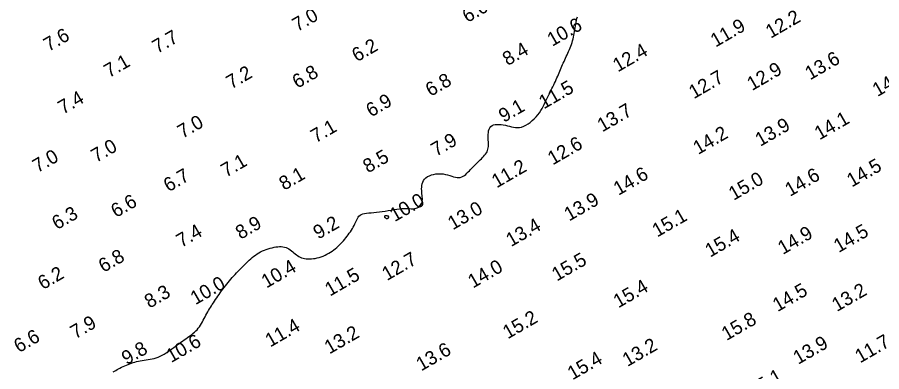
# Model space of a CAD drawing. Extents: x 3024098 to 3056816, y 418252 to 509144.
# Drawn here: x 3034302.4 to 3034614.7, y 418892.7 to 419020.7 of the extents above; entities that cross this region are included whole.
import ezdxf

# ---------------------------------------------------------------- set-up
doc = ezdxf.new("R2010")
doc.units = 0
doc.layers.add('V-CHAN-CONT-EL10', color=7, linetype='Continuous')
doc.layers.add('V-TOPO-SOUN-0911', color=7, linetype='Continuous')

msp = doc.modelspace()

# ---------------------------------------------------------------- linework, layer by layer
at = {"layer": 'V-CHAN-CONT-EL10'}
msp.add_lwpolyline([(3034337.08, 418892.58), (3034337.52, 418892.88), (3034337.98, 418893.16), (3034338.47, 418893.45), (3034338.98, 418893.74), (3034339.52, 418894.02), (3034340.08, 418894.3), (3034340.65, 418894.57), (3034341.24, 418894.83), (3034341.83, 418895.09), (3034342.44, 418895.33), (3034343.04, 418895.56), (3034343.65, 418895.78), (3034344.27, 418895.98), (3034344.9, 418896.17), (3034345.53, 418896.34), (3034346.18, 418896.5), (3034346.85, 418896.64), (3034347.53, 418896.77), (3034348.23, 418896.87), (3034348.94, 418896.97), (3034349.67, 418897.08), (3034350.4, 418897.19), (3034351.14, 418897.33), (3034351.88, 418897.49), (3034352.62, 418897.7), (3034353.36, 418897.96), (3034354.08, 418898.27), (3034354.8, 418898.64), (3034355.51, 418899.05), (3034356.21, 418899.49), (3034356.91, 418899.96), (3034357.59, 418900.44), (3034358.26, 418900.93), (3034358.93, 418901.43), (3034359.59, 418901.91), (3034360.23, 418902.39), (3034360.87, 418902.85), (3034361.5, 418903.31), (3034362.11, 418903.75), (3034362.71, 418904.18), (3034363.3, 418904.6), (3034363.87, 418905.01), (3034364.43, 418905.4), (3034364.97, 418905.78), (3034365.49, 418906.17), (3034366, 418906.56), (3034366.48, 418906.97), (3034366.94, 418907.4), (3034367.39, 418907.86), (3034367.81, 418908.35), (3034368.21, 418908.89), (3034368.59, 418909.45), (3034368.95, 418910.05), (3034369.29, 418910.66), (3034369.62, 418911.29), (3034369.95, 418911.91), (3034370.27, 418912.53), (3034370.58, 418913.13), (3034370.89, 418913.72), (3034371.21, 418914.28), (3034371.52, 418914.83), (3034371.85, 418915.38), (3034372.18, 418915.92), (3034372.52, 418916.46), (3034372.88, 418917.01), (3034373.25, 418917.57), (3034373.63, 418918.15), (3034374.03, 418918.74), (3034374.45, 418919.35), (3034374.88, 418919.96), (3034375.32, 418920.58), (3034375.77, 418921.21), (3034376.23, 418921.84), (3034376.69, 418922.47), (3034377.17, 418923.09), (3034377.65, 418923.72), (3034378.13, 418924.33), (3034378.62, 418924.94), (3034379.11, 418925.54), (3034379.6, 418926.13), (3034380.1, 418926.71), (3034380.6, 418927.27), (3034381.11, 418927.82), (3034381.61, 418928.36), (3034382.12, 418928.88), (3034382.63, 418929.4), (3034383.14, 418929.91), (3034383.65, 418930.42), (3034384.15, 418930.93), (3034384.67, 418931.43), (3034385.18, 418931.94), (3034385.69, 418932.45), (3034386.21, 418932.95), (3034386.74, 418933.44), (3034387.28, 418933.91), (3034387.85, 418934.37), (3034388.43, 418934.81), (3034389.03, 418935.22), (3034389.66, 418935.6), (3034390.31, 418935.95), (3034390.99, 418936.27), (3034391.67, 418936.56), (3034392.37, 418936.82), (3034393.07, 418937.06), (3034393.77, 418937.27), (3034394.47, 418937.45), (3034395.16, 418937.6), (3034395.84, 418937.72), (3034396.5, 418937.81), (3034397.15, 418937.86), (3034397.78, 418937.86), (3034398.39, 418937.81), (3034398.97, 418937.7), (3034399.52, 418937.54), (3034400.05, 418937.31), (3034400.54, 418937.03), (3034401.02, 418936.71), (3034401.48, 418936.36), (3034401.92, 418935.99), (3034402.36, 418935.62), (3034402.8, 418935.26), (3034403.24, 418934.91), (3034403.69, 418934.6), (3034404.15, 418934.32), (3034404.63, 418934.07), (3034405.12, 418933.86), (3034405.64, 418933.69), (3034406.18, 418933.56), (3034406.76, 418933.46), (3034407.36, 418933.41), (3034408, 418933.4), (3034408.68, 418933.43), (3034409.37, 418933.51), (3034410.08, 418933.62), (3034410.8, 418933.77), (3034411.52, 418933.96), (3034412.23, 418934.18), (3034412.94, 418934.45), (3034413.62, 418934.74), (3034414.28, 418935.07), (3034414.93, 418935.43), (3034415.55, 418935.81), (3034416.15, 418936.22), (3034416.73, 418936.64), (3034417.29, 418937.09), (3034417.83, 418937.54), (3034418.35, 418938.01), (3034418.85, 418938.49), (3034419.34, 418938.97), (3034419.81, 418939.47), (3034420.26, 418939.98), (3034420.7, 418940.5), (3034421.13, 418941.03), (3034421.55, 418941.57), (3034421.96, 418942.12), (3034422.36, 418942.67), (3034422.75, 418943.23), (3034423.12, 418943.8), (3034423.46, 418944.36), (3034423.79, 418944.92), (3034424.09, 418945.48), (3034424.36, 418946.03), (3034424.6, 418946.57), (3034424.82, 418947.09), (3034425.04, 418947.58), (3034425.27, 418948.04), (3034425.54, 418948.47), (3034425.86, 418948.85), (3034426.24, 418949.18), (3034426.71, 418949.45), (3034427.26, 418949.66), (3034427.9, 418949.81), (3034428.63, 418949.93), (3034429.43, 418950.01), (3034430.3, 418950.09), (3034431.22, 418950.16), (3034432.2, 418950.25), (3034433.22, 418950.36), (3034434.28, 418950.51), (3034435.36, 418950.68), (3034436.44, 418950.87), (3034437.51, 418951.06), (3034438.56, 418951.24), (3034439.56, 418951.4), (3034440.51, 418951.53), (3034441.39, 418951.62), (3034442.18, 418951.65), (3034442.9, 418951.64), (3034443.54, 418951.61), (3034444.13, 418951.56), (3034444.67, 418951.52), (3034445.16, 418951.5), (3034445.63, 418951.51), (3034446.08, 418951.57), (3034446.51, 418951.69), (3034446.92, 418951.87), (3034447.31, 418952.11), (3034447.67, 418952.39), (3034447.98, 418952.72), (3034448.25, 418953.08), (3034448.47, 418953.48), (3034448.63, 418953.91), (3034448.73, 418954.35), (3034448.77, 418954.83), (3034448.77, 418955.32), (3034448.73, 418955.83), (3034448.68, 418956.36), (3034448.62, 418956.92), (3034448.56, 418957.5), (3034448.52, 418958.09), (3034448.5, 418958.71), (3034448.52, 418959.33), (3034448.59, 418959.95), (3034448.72, 418960.57), (3034448.92, 418961.16), (3034449.19, 418961.72), (3034449.56, 418962.23), (3034450.03, 418962.7), (3034450.61, 418963.11), (3034451.28, 418963.45), (3034452.03, 418963.73), (3034452.83, 418963.94), (3034453.67, 418964.08), (3034454.54, 418964.16), (3034455.41, 418964.16), (3034456.26, 418964.08), (3034457.08, 418963.94), (3034457.87, 418963.74), (3034458.63, 418963.52), (3034459.35, 418963.29), (3034460.04, 418963.07), (3034460.69, 418962.9), (3034461.32, 418962.79), (3034461.9, 418962.76), (3034462.46, 418962.84), (3034462.98, 418963.01), (3034463.48, 418963.26), (3034463.96, 418963.58), (3034464.42, 418963.95), (3034464.87, 418964.36), (3034465.31, 418964.8), (3034465.75, 418965.25), (3034466.18, 418965.7), (3034466.61, 418966.15), (3034467.04, 418966.59), (3034467.48, 418967.03), (3034467.91, 418967.46), (3034468.34, 418967.89), (3034468.77, 418968.32), (3034469.21, 418968.74), (3034469.65, 418969.16), (3034470.08, 418969.57), (3034470.5, 418969.99), (3034470.89, 418970.4), (3034471.26, 418970.82), (3034471.59, 418971.24), (3034471.89, 418971.66), (3034472.13, 418972.1), (3034472.31, 418972.55), (3034472.45, 418973.01), (3034472.54, 418973.48), (3034472.6, 418973.98), (3034472.62, 418974.51), (3034472.62, 418975.06), (3034472.61, 418975.65), (3034472.58, 418976.28), (3034472.56, 418976.94), (3034472.55, 418977.63), (3034472.56, 418978.32), (3034472.61, 418979), (3034472.71, 418979.64), (3034472.88, 418980.23), (3034473.14, 418980.76), (3034473.48, 418981.2), (3034473.93, 418981.53), (3034474.46, 418981.77), (3034475.08, 418981.92), (3034475.76, 418981.99), (3034476.48, 418982), (3034477.23, 418981.94), (3034477.99, 418981.84), (3034478.75, 418981.69), (3034479.5, 418981.52), (3034480.23, 418981.33), (3034480.96, 418981.15), (3034481.68, 418980.99), (3034482.4, 418980.89), (3034483.13, 418980.85), (3034483.87, 418980.89), (3034484.62, 418981.04), (3034485.4, 418981.31), (3034486.18, 418981.69), (3034486.96, 418982.17), (3034487.73, 418982.72), (3034488.48, 418983.35), (3034489.19, 418984.02), (3034489.87, 418984.73), (3034490.48, 418985.47), (3034491.04, 418986.21), (3034491.54, 418986.96), (3034491.99, 418987.71), (3034492.4, 418988.47), (3034492.79, 418989.22), (3034493.15, 418989.96), (3034493.5, 418990.7), (3034493.84, 418991.43), (3034494.19, 418992.15), (3034494.53, 418992.85), (3034494.88, 418993.54), (3034495.22, 418994.23), (3034495.56, 418994.9), (3034495.89, 418995.57), (3034496.22, 418996.22), (3034496.53, 418996.87), (3034496.82, 418997.51), (3034497.11, 418998.15), (3034497.38, 418998.77), (3034497.65, 418999.39), (3034497.9, 419000.01), (3034498.16, 419000.61), (3034498.41, 419001.22), (3034498.66, 419001.81), (3034498.91, 419002.4), (3034499.17, 419002.99), (3034499.42, 419003.57), (3034499.68, 419004.15), (3034499.94, 419004.73), (3034500.21, 419005.32), (3034500.48, 419005.91), (3034500.76, 419006.51), (3034501.04, 419007.11), (3034501.32, 419007.72), (3034501.6, 419008.34), (3034501.88, 419008.97), (3034502.15, 419009.6), (3034502.4, 419010.24), (3034502.64, 419010.89), (3034502.85, 419011.54), (3034503.04, 419012.2), (3034503.21, 419012.86), (3034503.36, 419013.53), (3034503.5, 419014.19), (3034503.63, 419014.86), (3034503.75, 419015.53), (3034503.86, 419016.2), (3034503.97, 419016.87), (3034504.09, 419017.54), (3034504.21, 419018.2), (3034504.34, 419018.86), (3034504.47, 419019.52), (3034504.62, 419020.18), (3034504.79, 419020.84)], dxfattribs=at)
msp.add_lwpolyline([(3034435.77, 418948.01), (3034435.88, 418947.99), (3034435.98, 418947.99), (3034436.07, 418948), (3034436.16, 418948.03), (3034436.25, 418948.07), (3034436.32, 418948.12), (3034436.39, 418948.17), (3034436.46, 418948.23), (3034436.51, 418948.28), (3034436.56, 418948.34), (3034436.6, 418948.4), (3034436.63, 418948.46), (3034436.65, 418948.51), (3034436.67, 418948.57), (3034436.68, 418948.61), (3034436.67, 418948.66), (3034436.66, 418948.7), (3034436.63, 418948.74), (3034436.58, 418948.77), (3034436.52, 418948.8), (3034436.44, 418948.83), (3034436.34, 418948.86), (3034436.21, 418948.89), (3034436.06, 418948.91), (3034435.9, 418948.93), (3034435.73, 418948.94), (3034435.56, 418948.94), (3034435.4, 418948.93), (3034435.26, 418948.91), (3034435.15, 418948.87), (3034435.08, 418948.81), (3034435.05, 418948.73), (3034435.07, 418948.64), (3034435.12, 418948.53), (3034435.2, 418948.42), (3034435.3, 418948.31), (3034435.41, 418948.21), (3034435.53, 418948.12), (3034435.65, 418948.06)], close=True, dxfattribs=at)

# ---------------------------------------------------------------- texts
at = {"layer": 'V-TOPO-SOUN-0911'}
for s, p in [('6.0', (3034465.03, 419018.55)), ('7.0', (3034403.58, 419015.33)), ('12.2 ', (3034574.59, 419012.87)), ('10.6 ', (3034495.69, 419009.99)), ('11.9 ', (3034554.68, 419009.69)), ('7.6', (3034313.73, 419008.12)), ('7.7', (3034353, 419007.4)), ('6.2', (3034425.12, 419004.38)), ('8.4', (3034479.55, 419003)), ('12.4 ', (3034519.38, 419000.73)), ('13.6 ', (3034588.83, 418997.85)), ('7.1', (3034335.56, 418998.65)), ('12.9 ', (3034567.87, 418994)), ('7.2', (3034379.71, 418994.57)), ('6.8', (3034403.59, 418994.8)), ('12.7 ', (3034546.84, 418991.05)), ('14.7 ', (3034613.17, 418991.84)), ('6.8', (3034451.72, 418991.88)), ('11.5 ', (3034492.66, 418987.38)), ('7.4', (3034318.95, 418985.48)), ('6.9', (3034430.23, 418984.46)), ('9.1', (3034478.15, 418982.51)), ('13.7 ', (3034513.77, 418979.08)), ('7.0', (3034362.11, 418976.75)), ('14.1 ', (3034592.23, 418976.2)), ('7.1', (3034410.24, 418975.13)), ('13.9 ', (3034570.82, 418973.86)), ('14.2 ', (3034548.38, 418970.91)), ('7.0', (3034330.91, 418968.06)), ('7.9', (3034453.73, 418970.26)), ('12.6 ', (3034495.85, 418967.14)), ('7.0', (3034309.75, 418964.35)), ('8.5', (3034429.11, 418964.25)), ('7.1', (3034377.82, 418962.73)), ('14.5 ', (3034603.91, 418959.16)), ('11.2 ', (3034475.61, 418958.87)), ('14.6 ', (3034519.6, 418956.18)), ('6.7', (3034357.07, 418957.43)), ('8.1', (3034398.82, 418958)), ('15.0 ', (3034561.22, 418954.37)), ('14.6 ', (3034581.58, 418955.79)), ('13.9 ', (3034501.79, 418946.89)), ('6.6', (3034338.07, 418948.15)), ('10.0 ', (3034438.75, 418946.66)), ('13.0 ', (3034459.75, 418943.71)), ('6.3', (3034316.75, 418943.78)), ('15.1 ', (3034533.6, 418941.1)), ('8.9', (3034383.09, 418940.3)), ('9.2', (3034411.14, 418940.34)), ('13.4 ', (3034480.79, 418937.64)), ('7.4', (3034361.67, 418937.35)), ('14.9 ', (3034578.99, 418934.82)), ('14.5 ', (3034599.16, 418935.51)), ('15.4 ', (3034552.71, 418933.83)), ('6.8', (3034333.58, 418928.33)), ('12.7 ', (3034435.98, 418925.4)), ('15.5 ', (3034497.32, 418925.2)), ('10.4 ', (3034392.41, 418922.68)), ('14.0 ', (3034467.03, 418922.68)), ('6.2', (3034311.67, 418922.13)), ('11.5 ', (3034415.36, 418919.76)), ('10.0 ', (3034366.77, 418916.67)), ('15.4 ', (3034519.57, 418915.53)), ('8.3', (3034350.18, 418915.43)), ('14.5 ', (3034577.11, 418914.18)), ('13.2 ', (3034598.51, 418914.21)), ('15.2 ', (3034479.61, 418904.34)), ('15.8 ', (3034558.65, 418903.75)), ('7.9', (3034323.38, 418904.34)), ('11.4 ', (3034393.79, 418901.39)), ('6.6', (3034303, 418899.36)), ('13.2 ', (3034415.18, 418898.89)), ('10.6 ', (3034358.02, 418895.78)), ('13.2 ', (3034522.85, 418894.36)), ('13.9 ', (3034584.53, 418895.15)), ('11.7 ', (3034606.88, 418895.64)), ('9.8', (3034341.91, 418894.99)), ('13.6 ', (3034448.34, 418892.76)), ('15.4 ', (3034503, 418889.54)), ('15.1 ', (3034568.08, 418883.22))]:
    msp.add_text(s, height=5, rotation=30, dxfattribs=at).set_placement(p)

doc.saveas('drawing.dxf')
